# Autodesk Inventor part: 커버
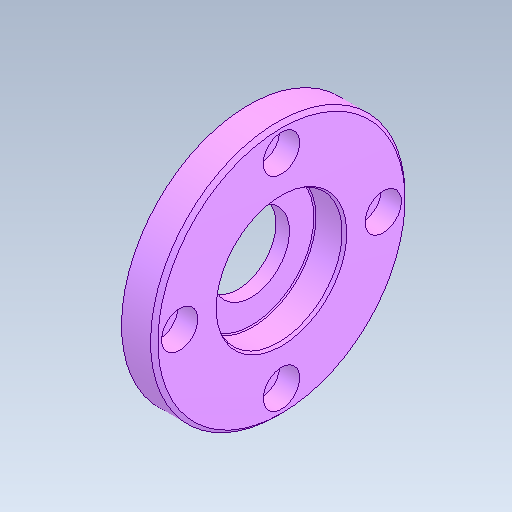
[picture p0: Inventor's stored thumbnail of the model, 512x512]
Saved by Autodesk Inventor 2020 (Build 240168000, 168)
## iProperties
Created: 2024-09
Part Number: 커버
Material: 알루미늄 6061
Document SubType Name: Modeling
Designer: oem
Density: 2.7 g/cm^3
Appearance: 기본값
Author: jhkim
Sending System: Autodesk Inventor 2025
Preprocessor: ST-DEVELOPER v20
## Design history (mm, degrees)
feature "솔리드1"
node "솔리드2"
